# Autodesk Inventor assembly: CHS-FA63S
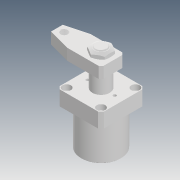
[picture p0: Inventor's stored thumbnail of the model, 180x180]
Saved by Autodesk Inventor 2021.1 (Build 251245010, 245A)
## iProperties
Created: 2019-05
Part Number: CHS-FA63S
Description: STEP AP203
Document SubType Name: Assembly
Designer: user
Title: chs-fa63s_asm.STEP
Revision Number: ÈÎºÎ
Sending System: SolidWorks 2017
Preprocessor: SwSTEP 2.0
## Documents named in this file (5)
- D:\Vault_2016\Projekty\Clamptek\Hydraulic\CHS\CHS-63\Inventor\CHS-FA63S\CHS-FA63S.iam
- D:\Vault_2016\Projekty\Clamptek\Hydraulic\CHS\CHS-63\Inventor\CHS-FA63S\CHS-FA63-03_1.ipt
- D:\Vault_2016\Projekty\Clamptek\Hydraulic\CHS\CHS-63\Inventor\CHS-FA63S\CHS-63S-02_1_1.ipt
- D:\Vault_2016\Projekty\Clamptek\Hydraulic\CHS\CHS-63\Inventor\CHS-FA63S\CHS-63S-01_1.ipt
- D:\Vault_2016\Projekty\Clamptek\Hydraulic\CHS\CHS-63\Inventor\CHS-FA63S\M24_1.ipt
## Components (4 placed, 4 different names)
1. CHS-FA63-03_1_1
2. CHS-63S-02_1_1_2
3. CHS-63S-01_1_3
4. M24_1_4
